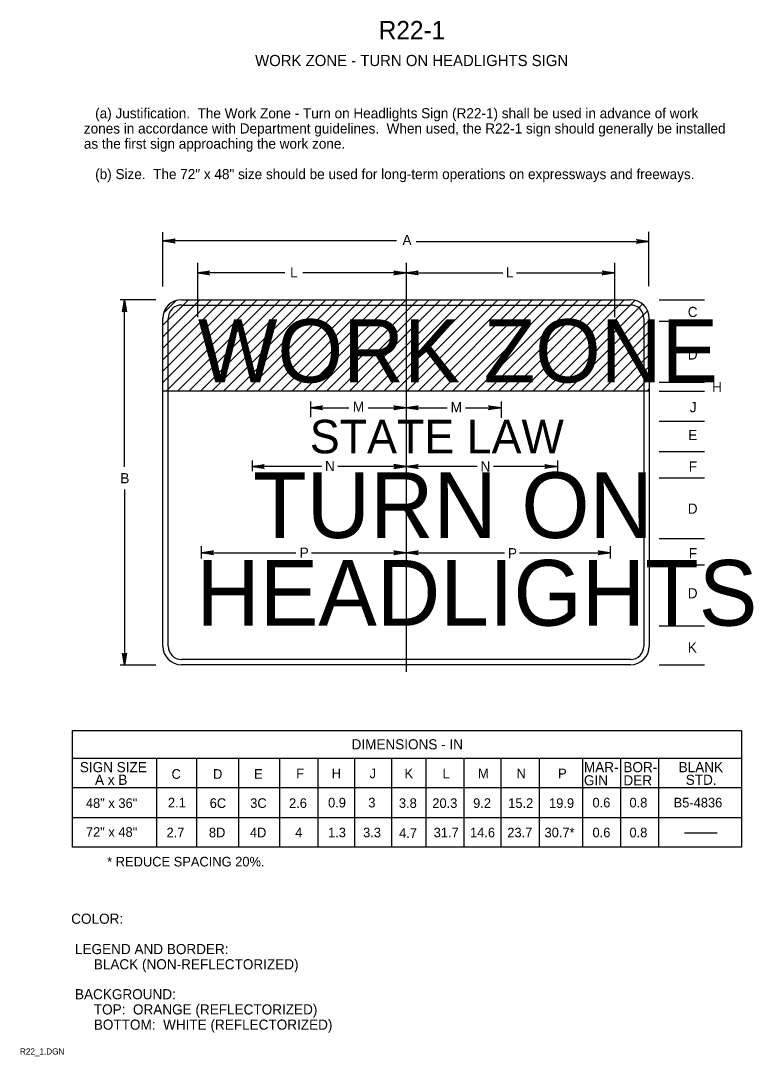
# Model space of a CAD drawing. Extents: x 0.013 to 0.193, y 0.004 to 0.259.
import ezdxf

# ---------------------------------------------------------------- set-up
doc = ezdxf.new("R2010")
doc.units = 0
for name, color, linetype in [('1', 7, 'Continuous'), ('2', 7, 'Continuous'), ('3', 7, 'Continuous')]:
    doc.layers.add(name, color=color, linetype=linetype)

# ---------------------------------------------------------------- blocks, each defined once
blk = doc.blocks.new('RARROW')
at = {"layer": '3'}
for p, q in [((-2.156, 0.285), (-2.2665, 0.384625)), ((-2.2665, 0.384625), (0, 0)), ((0, 0), (-2.2665, -0.379125)), ((-2.156, 0.285), (-2.075625, 0.12075)), ((0, 0), (-2.156, 0.285)), ((-2.14975, -0.2705), (0, 0)), ((-2.075625, 0.12075), (0, 0)), ((0, 0), (-2.074, -0.108)), ((-2.2665, -0.379125), (-2.14975, -0.2705)), ((-2.074, -0.108), (-2.14975, -0.2705))]:
    blk.add_line(p, q, dxfattribs=at)

msp = doc.modelspace()

# ---------------------------------------------------------------- linework, layer by layer
at = {"layer": '1'}
for p, q in [((0.05625, 0.19959), (0.05625, 0.18619)), ((0.10775, 0.19959), (0.10775, 0.09875)), ((0.15914, 0.19959), (0.15914, 0.18619)), ((0.04767, 0.18412), (0.05405, 0.1905)), ((0.04767, 0.18129), (0.05688, 0.1905)), ((0.04767, 0.17847), (0.05971, 0.1905)), ((0.04767, 0.17564), (0.06254, 0.1905)), ((0.04767, 0.17281), (0.06536, 0.1905)), ((0.04767, 0.16998), (0.06819, 0.1905)), ((0.04792, 0.1872), (0.05104, 0.19032)), ((0.04852, 0.168), (0.07102, 0.1905)), ((0.05135, 0.168), (0.07385, 0.1905)), ((0.05418, 0.168), (0.07668, 0.1905)), ((0.05701, 0.168), (0.07951, 0.1905)), ((0.05984, 0.168), (0.08234, 0.1905)), ((0.06266, 0.168), (0.08516, 0.1905)), ((0.06549, 0.168), (0.08799, 0.1905)), ((0.06832, 0.168), (0.09082, 0.1905)), ((0.07115, 0.168), (0.09365, 0.1905)), ((0.07398, 0.168), (0.09648, 0.1905)), ((0.07681, 0.168), (0.09931, 0.1905)), ((0.07963, 0.168), (0.10213, 0.1905)), ((0.08246, 0.168), (0.10496, 0.1905)), ((0.08529, 0.168), (0.10779, 0.1905)), ((0.08812, 0.168), (0.11062, 0.1905)), ((0.09095, 0.168), (0.11345, 0.1905)), ((0.09378, 0.168), (0.11628, 0.1905)), ((0.0966, 0.168), (0.1191, 0.1905)), ((0.09943, 0.168), (0.12193, 0.1905)), ((0.10226, 0.168), (0.12476, 0.1905)), ((0.10509, 0.168), (0.12759, 0.1905)), ((0.10792, 0.168), (0.13042, 0.1905)), ((0.11075, 0.168), (0.13325, 0.1905)), ((0.11358, 0.168), (0.13608, 0.1905)), ((0.1164, 0.168), (0.1389, 0.1905)), ((0.11923, 0.168), (0.14173, 0.1905)), ((0.12206, 0.168), (0.14456, 0.1905)), ((0.12489, 0.168), (0.14739, 0.1905)), ((0.12772, 0.168), (0.15022, 0.1905)), ((0.13055, 0.168), (0.15305, 0.1905)), ((0.13337, 0.168), (0.15587, 0.1905)), ((0.1362, 0.168), (0.1587, 0.1905)), ((0.13903, 0.168), (0.16153, 0.1905)), ((0.14186, 0.168), (0.16423, 0.19037)), ((0.14469, 0.168), (0.1661, 0.18941)), ((0.14752, 0.168), (0.16732, 0.1878)), ((0.15035, 0.168), (0.16773, 0.18539)), ((0.15317, 0.168), (0.16773, 0.18256)), ((0.156, 0.168), (0.16773, 0.17973)), ((0.15883, 0.168), (0.16773, 0.1769)), ((0.16166, 0.168), (0.16773, 0.17407)), ((0.16449, 0.168), (0.16773, 0.17125)), ((0.16732, 0.168), (0.16773, 0.16842)), ((0.08414, 0.16541), (0.08414, 0.16159)), ((0.1312, 0.16542), (0.1312, 0.16138)), ((0.06976, 0.15087), (0.06976, 0.14821)), ((0.14507, 0.15087), (0.14507, 0.14817)), ((0.05723, 0.1297), (0.05723, 0.1267)), ((0.15814, 0.1297), (0.15814, 0.1267)), ((0.1905, 0.08425), (0.1905, 0.0555)), ((0.15125, 0.07735), (0.15125, 0.05547)), ((0.16062, 0.07735), (0.16062, 0.05547)), ((0.17, 0.07735), (0.17, 0.05547))]:
    msp.add_line(p, q, dxfattribs=at)
at = {"layer": '2'}
for p, q in [((0.05233, 0.1905), (0.16313, 0.1905)), ((0.04773, 0.1051), (0.04773, 0.1859)), ((0.16773, 0.1859), (0.16773, 0.1051)), ((0.16773, 0.168), (0.04773, 0.168)), ((0.16313, 0.1005), (0.05233, 0.1005)), ((0.02538, 0.08425), (0.1905, 0.08425)), ((0.02538, 0.08425), (0.02538, 0.0555)), ((0.1905, 0.07737), (0.02538, 0.07737)), ((0.04616, 0.07738), (0.04616, 0.0555)), ((0.056, 0.07737), (0.056, 0.0555)), ((0.06638, 0.07737), (0.06638, 0.0555)), ((0.0765, 0.07737), (0.0765, 0.0555)), ((0.086, 0.07737), (0.086, 0.0555)), ((0.095, 0.07737), (0.095, 0.0555)), ((0.10412, 0.07737), (0.10412, 0.0555)), ((0.11263, 0.07737), (0.11263, 0.0555)), ((0.122, 0.07737), (0.122, 0.0555)), ((0.13112, 0.07737), (0.13112, 0.0555)), ((0.14062, 0.07737), (0.14062, 0.0555)), ((0.1905, 0.07013), (0.02538, 0.07013)), ((0.1905, 0.06275), (0.02538, 0.06275)), ((0.1905, 0.0555), (0.02538, 0.0555))]:
    msp.add_line(p, q, dxfattribs=at)
for centre, start, end in [((0.05233, 0.1859), 90, 180), ((0.16313, 0.1859), 0, 90), ((0.05233, 0.1051), 180, 270), ((0.16313, 0.1051), 270, 0)]:
    msp.add_arc(centre, 0.0046, start, end, dxfattribs=at)
at = {"layer": '3'}
for p, q in [((0.04773, 0.19381), (0.04773, 0.20721)), ((0.16763, 0.19382), (0.16763, 0.20722)), ((0.10536, 0.205), (0.04775, 0.205)), ((0.11027, 0.20488), (0.16762, 0.20488)), ((0.07787, 0.19712), (0.05625, 0.19712)), ((0.10775, 0.19712), (0.08229, 0.19712)), ((0.10775, 0.19712), (0.13162, 0.19712)), ((0.13502, 0.19712), (0.15913, 0.19712)), ((0.04598, 0.1905), (0.03723, 0.1905)), ((0.03825, 0.1493), (0.03825, 0.1905)), ((0.05233, 0.1892), (0.16313, 0.1892)), ((0.17023, 0.1905), (0.18136, 0.1905)), ((0.04903, 0.1051), (0.04903, 0.1859)), ((0.16643, 0.1859), (0.16643, 0.1051)), ((0.17023, 0.1852), (0.18136, 0.1852)), ((0.17023, 0.1702), (0.18136, 0.1702)), ((0.17023, 0.168), (0.18136, 0.168)), ((0.08414, 0.16387), (0.09362, 0.16387)), ((0.09838, 0.16387), (0.11788, 0.16387)), ((0.12237, 0.16387), (0.1312, 0.16387)), ((0.17023, 0.1606), (0.18136, 0.1606)), ((0.17023, 0.1531), (0.18136, 0.1531)), ((0.0869, 0.14939), (0.06975, 0.14939)), ((0.10775, 0.14938), (0.09089, 0.14938)), ((0.12525, 0.14938), (0.10775, 0.14938)), ((0.14507, 0.14938), (0.12931, 0.14938)), ((0.17023, 0.1466), (0.18136, 0.1466)), ((0.03825, 0.14373), (0.03825, 0.10038)), ((0.17023, 0.1316), (0.18136, 0.1316)), ((0.05725, 0.12812), (0.08052, 0.12812)), ((0.08438, 0.12812), (0.10775, 0.12812)), ((0.10775, 0.12812), (0.132, 0.12812)), ((0.13575, 0.12812), (0.15813, 0.12812)), ((0.17023, 0.1251), (0.18136, 0.1251)), ((0.17023, 0.1101), (0.18136, 0.1101)), ((0.04599, 0.10038), (0.03724, 0.10038)), ((0.16313, 0.1018), (0.05233, 0.1018)), ((0.17023, 0.1005), (0.18136, 0.1005)), ((0.17641, 0.05902), (0.18449, 0.05902))]:
    msp.add_line(p, q, dxfattribs=at)
for centre, start, end in [((0.05233, 0.1859), 90, 180), ((0.16313, 0.1859), 0, 90), ((0.05233, 0.1051), 180, 270), ((0.16313, 0.1051), 270, 0)]:
    msp.add_arc(centre, 0.0033, start, end, dxfattribs=at)

# ---------------------------------------------------------------- block references
at = {"layer": '3', "xscale": 0.0013236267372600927, "yscale": 0.001309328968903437}
for p, rotation in [((0.04775, 0.205), 180), ((0.05625, 0.19712), 180), ((0.10775, 0.19712), 180), ((0.03825, 0.1905), 90), ((0.08413, 0.16387), 180), ((0.10775, 0.16387), 180), ((0.06975, 0.14938), 180), ((0.10775, 0.14938), 180), ((0.05725, 0.12812), 180), ((0.10775, 0.12812), 180), ((0.03825, 0.10038), -90)]:
    msp.add_blockref('RARROW', p, dxfattribs=dict(at, rotation=rotation))
at = {"layer": '3', "xscale": 0.0013236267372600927}
for p, yscale in [((0.16762, 0.20488), 0.001309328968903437), ((0.10775, 0.19712), 0.001309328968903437), ((0.15913, 0.19712), 0.001309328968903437), ((0.10775, 0.16387), 0.001309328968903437), ((0.13112, 0.16387), 0.001309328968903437), ((0.10775, 0.14938), -0.001309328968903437), ((0.145, 0.14938), 0.001309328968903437), ((0.10775, 0.12812), 0.001309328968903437), ((0.15813, 0.12812), 0.001309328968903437)]:
    msp.add_blockref('RARROW', p, dxfattribs=dict(at, yscale=yscale))

# ---------------------------------------------------------------- texts
at = {"layer": '1'}
for s, height, p in [('R22-1', 0.0045, (0.101, 0.25475)), ('WORK ZONE - TURN ON HEADLIGHTS SIGN', 0.0027503, (0.0705, 0.24813)), ('WORK ZONE', 0.015559, (0.05638, 0.17012)), ('STATE LAW', 0.008268, (0.084, 0.15263)), ('TURN ON', 0.016198, (0.07, 0.13175)), ('HEADLIGHTS', 0.016198, (0.056, 0.11013)), ('MAR-', 0.0025, (0.15163, 0.074)), ('BOR-', 0.0025, (0.16137, 0.074)), ('BLANK', 0.0025, (0.175, 0.074)), ('GIN', 0.0025, (0.15163, 0.07075)), ('DER', 0.0025, (0.16137, 0.07075)), ('STD.', 0.0025, (0.17675, 0.07088)), ('B5-4836', 0.002375, (0.17376, 0.06531)), ('COLOR:', 0.0025, (0.02513, 0.03662)), (' LEGEND AND BORDER:', 0.0024998, (0.02513, 0.02913)), ('      BLACK (NON-REFLECTORIZED)', 0.0024998, (0.02513, 0.02538)), (' BACKGROUND:', 0.0024998, (0.02513, 0.018)), ('      TOP:  ORANGE (REFLECTORIZED)', 0.0024998, (0.02513, 0.01425)), ('      BOTTOM:  WHITE (REFLECTORIZED)', 0.0024998, (0.02513, 0.0105)), ('R22_1.DGN', 0.0015, (0.0125, 0.00438))]:
    msp.add_text(s, height=height, dxfattribs=at).set_placement(p)
at = {"layer": '2'}
for s, height, p in [('   (a) Justification.  The Work Zone - Turn on Headlights Sign (R22-1) shall be used in advance of work', 0.00249975, (0.02825, 0.23525)), ('zones in accordance with Department guidelines.  When used, the R22-1 sign should generally be installed', 0.00249975, (0.02825, 0.2315)), ('as the first sign approaching the work zone.', 0.0024998, (0.02825, 0.22775)), ('   (b) Size.  The 72" x 48" size should be used for long-term operations on expressways and freeways.', 0.00249975, (0.02825, 0.22025)), ('DIMENSIONS - IN', 0.0024998, (0.0943, 0.07963)), ('SIGN SIZE', 0.0025, (0.02725, 0.074)), ('C', 0.00238, (0.04988, 0.07237)), ('D', 0.00238, (0.06012, 0.07237)), ('E', 0.00238, (0.07025, 0.07237)), ('F', 0.00238, (0.08063, 0.0725)), ('H', 0.00238, (0.08937, 0.0725)), ('J', 0.00238, (0.09875, 0.0725)), ('K', 0.00238, (0.10737, 0.0725)), ('L', 0.00238, (0.11675, 0.0725)), ('M', 0.00238, (0.1255, 0.0725)), ('N', 0.00238, (0.135, 0.0725)), ('P', 0.00238, (0.14525, 0.0725)), ('A x B', 0.0025, (0.031, 0.07088))]:
    msp.add_text(s, height=height, dxfattribs=at).set_placement(p)
at = {"layer": '3'}
for s, height, p in [('A', 0.0025, (0.10687, 0.204)), ('L', 0.0025, (0.07913, 0.196)), ('L', 0.0025, (0.13237, 0.196)), ('C', 0.0025, (0.17725, 0.18625)), ('D', 0.0025, (0.17725, 0.17575)), ('H', 0.0025, (0.18325, 0.16775)), ('M', 0.0025, (0.09463, 0.16287)), ('M', 0.0025, (0.11875, 0.16275)), ('J', 0.0025, (0.17775, 0.16275)), ('E', 0.0025, (0.17738, 0.15588)), ('N', 0.0025, (0.08775, 0.14825)), ('N', 0.0025, (0.12613, 0.14813)), ('F', 0.0025, (0.1775, 0.14813)), ('B', 0.0025, (0.03725, 0.14525)), ('D', 0.0025, (0.17725, 0.13775)), ('P', 0.0025, (0.0815, 0.12688)), ('P', 0.0025, (0.13287, 0.12675)), ('F', 0.0025, (0.1775, 0.12675)), ('D', 0.0025, (0.17725, 0.11688)), ('K', 0.0025, (0.17725, 0.1035)), ('48" x 36"', 0.002375, (0.02875, 0.06519)), ('2.1', 0.002375, (0.04899, 0.06531)), ('6C', 0.002375, (0.05929, 0.06519)), ('3C', 0.002375, (0.06929, 0.06519)), ('2.6', 0.002375, (0.07887, 0.06519)), ('0.9', 0.002375, (0.0885, 0.06531)), ('3', 0.00238, (0.09843, 0.06531)), ('3.8', 0.002375, (0.10598, 0.06519)), ('20.3', 0.002375, (0.11422, 0.06519)), ('9.2', 0.002375, (0.12429, 0.06519)), ('15.2', 0.002375, (0.13295, 0.06519)), ('19.9', 0.002375, (0.14303, 0.06519)), ('0.6', 0.002375, (0.15374, 0.06531)), ('0.8', 0.002375, (0.16286, 0.06531)), ('72" x 48"', 0.002375, (0.02875, 0.05806)), ('2.7', 0.002375, (0.04865, 0.05794)), ('8D', 0.002375, (0.0591, 0.05794)), ('4D', 0.002375, (0.06922, 0.05794)), ('4', 0.00238, (0.08039, 0.05794)), ('1.3', 0.002375, (0.08849, 0.05794)), ('3.3', 0.002375, (0.09715, 0.05794)), ('4.7', 0.002375, (0.10603, 0.05781)), ('31.7', 0.002375, (0.11456, 0.05794)), ('14.6', 0.002375, (0.12352, 0.05794)), ('23.7', 0.002375, (0.13272, 0.05794)), ('30.7*', 0.002375, (0.14191, 0.05794)), ('0.6', 0.002375, (0.15374, 0.05794)), ('0.8', 0.002375, (0.16286, 0.05794)), ('* REDUCE SPACING 20%.', 0.0023752, (0.034, 0.05075))]:
    msp.add_text(s, height=height, dxfattribs=at).set_placement(p)

doc.saveas('drawing.dxf')
